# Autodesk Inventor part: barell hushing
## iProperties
Created: 2006-04
Part Number: barell hushing
Document SubType Name: Modeling
Designer: Калинин
Author: Калинин
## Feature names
1. Выдавливание1 [Extrusion]
2. Отверстие1 [Hole]
3. Выдавливание2 [Extrusion]
4. Выдавливание3 [Extrusion]
5. Фаска1 [Chamfer]
6. Фаска2 [Chamfer]
7. Выдавливание4 [Extrusion]
8. Выдавливание5 [Extrusion]
9. Сопряжение1 [Fillet]
10. Сопряжение2 [Fillet]
11. Сопряжение3 [Fillet]
12. Сопряжение4 [Fillet]
13. Сопряжение5 [Fillet]
